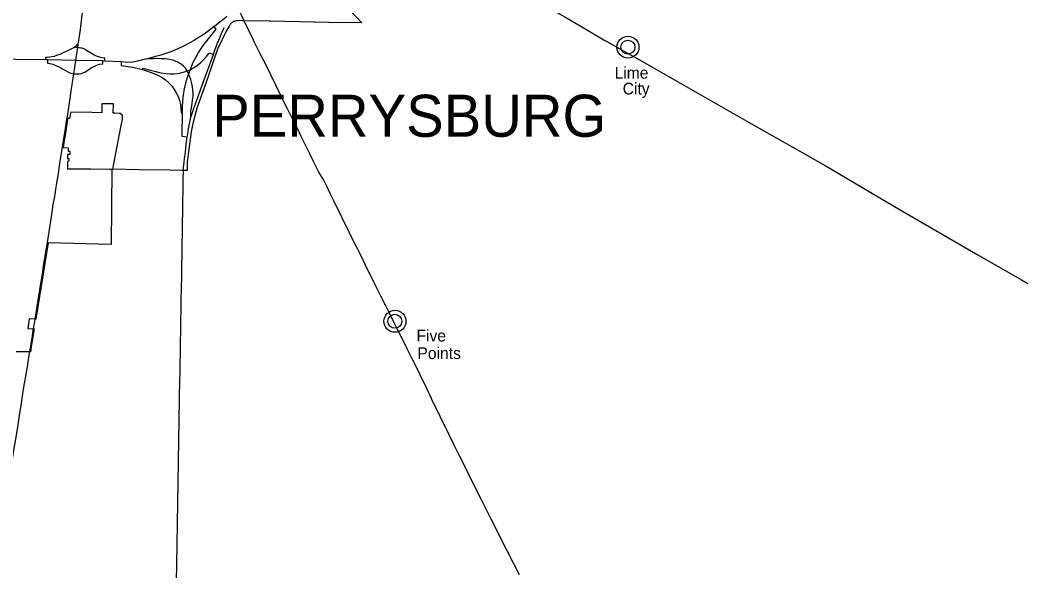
# Model space of a CAD drawing. Extents: x 0 to 851, y 0 to 440.
# Drawn here: x 318.5 to 378.4, y 277.3 to 310.2 of the extents above; entities that cross this region are included whole.
import ezdxf

# ---------------------------------------------------------------- set-up
doc = ezdxf.new("R2010")
doc.units = 0
for name, color, linetype in [('DV_X_Corp_Line', 7, 'Continuous'), ('GM_X_Corporation_Text', 7, 'Continuous'), ('GM_X_Interchange_Ramps', 7, 'Continuous'), ('GM_X_Interstate_Route', 7, 'Continuous'), ('GM_X_State_Route', 7, 'Continuous'), ('GM_X_US_Route', 7, 'Continuous')]:
    doc.layers.add(name, color=color, linetype=linetype)

msp = doc.modelspace()

# ---------------------------------------------------------------- linework, layer by layer
at = {"layer": 'DV_X_Corp_Line'}
msp.add_lwpolyline([(337.242, 311.829), (338.909, 310.055), (336.942, 310.078), (336.895, 310.078), (336.101, 310.09), (336.045, 310.09), (333.446, 310.144), (333.379, 310.145), (331.872, 310.178), (331.761, 310.178), (331.535, 310.182), (331.471, 310.18), (331.435, 310.177), (331.399, 310.172), (331.328, 310.155), (331.279, 310.138), (331.246, 310.123), (331.217, 310.107), (331.17, 310.077), (331.134, 310.051), (331.115, 310.035), (331.084, 310.004), (331.057, 309.973), (331.029, 309.936), (331.015, 309.916), (331.001, 309.894), (330.981, 309.857), (330.821, 309.598), (330.284, 308.48), (329.559, 306.323), (329.061, 304.951), (328.806, 304.038), (328.717, 303.553), (328.475, 301.76), (328.477, 301.238), (328.347, 301.238), (328.135, 301.241), (327.429, 301.254), (325.615, 301.283), (324.045, 301.309), (324.098, 301.63), (324.352, 302.983), (324.543, 303.915), (324.607, 304.272), (324.62, 304.515), (324.479, 304.63), (324.425, 304.64), (324.148, 304.651), (324.064, 304.653), (324.069, 305.218), (323.374, 305.218), (323.375, 304.672), (322.777, 304.695), (321.54, 304.726), (321.498, 304.567), (321.453, 304.338), (321.343, 304.338), (321.331, 304.289), (321.266, 303.88), (321.204, 303.471), (321.136, 303.034), (321.068, 302.601), (321.381, 302.591), (321.379, 302.396), (321.475, 302.395), (321.47, 302.184), (321.335, 302.187), (321.329, 301.964), (321.402, 301.964), (321.402, 301.794), (321.334, 301.783), (321.327, 301.737), (321.327, 301.341), (322.718, 301.329), (323.846, 301.311), (323.982, 301.309), (323.935, 296.813), (320.175, 296.928), (319.439, 292.37), (319.041, 292.378), (318.956, 291.817), (319.273, 291.787), (319.342, 291.787), (319.168, 290.718), (319.118, 290.411), (319.048, 290.414), (318.275, 290.42)], dxfattribs=at)
for centre, radius in [((354.787, 308.599), 0.658), ((354.787, 308.599), 0.417), ((340.876, 292.238), 0.658), ((340.876, 292.238), 0.417)]:
    msp.add_circle(centre, radius, dxfattribs=at)
at = {"layer": 'GM_X_Interchange_Ramps'}
for points in [[(321.975, 308.755), (321.913, 308.764), (321.857, 308.688), (321.801, 308.632), (321.724, 308.574), (321.604, 308.513), (320.866, 308.168), (320.678, 308.092), (320.541, 308.049), (320.397, 308.016), (320.265, 307.996), (320.09, 307.978), (320.022, 307.976), (320.02, 307.851)], [(321.949, 308.578), (321.884, 308.588), (321.789, 308.577), (321.733, 308.562), (321.724, 308.574)], [(323.557, 307.771), (323.559, 307.935), (323.414, 307.963), (323.242, 308.006), (323.069, 308.067), (322.861, 308.168), (322.656, 308.288), (322.428, 308.422), (322.301, 308.493), (322.199, 308.531), (322.123, 308.549), (322.037, 308.564), (321.949, 308.578)], [(320.133, 307.84), (320.13, 307.639), (320.283, 307.615), (320.465, 307.575), (320.64, 307.509), (320.856, 307.4), (321.383, 307.098), (321.464, 307.062), (321.538, 307.045), (321.639, 307.029), (321.708, 307.017)], [(321.708, 307.017), (321.793, 307.006), (321.923, 307.004), (322.03, 307.004), (322.154, 307.024), (322.253, 307.06), (322.359, 307.113), (322.75, 307.359), (322.904, 307.448), (323.013, 307.504), (323.127, 307.547), (323.252, 307.58), (323.376, 307.598), (323.436, 307.6), (323.44, 307.778)]]:
    msp.add_lwpolyline(points, dxfattribs=at)
at = {"layer": 'GM_X_Interstate_Route'}
for points in [[(321.825, 307.801), (320.133, 307.84), (320.02, 307.851), (312.929, 307.924), (311.76, 307.955), (311.222, 307.978), (310.795, 308.013), (310.42, 308.043), (310.05, 308.113), (309.736, 308.178), (309.383, 308.257), (309.023, 308.354), (308.624, 308.464), (308.248, 308.584), (307.869, 308.711), (307.566, 308.836), (307.238, 308.986), (306.945, 309.115), (306.66, 309.253), (306.342, 309.43), (306.144, 309.54)], [(328.702, 304.417), (328.778, 304.63), (328.876, 304.96), (328.985, 305.279), (329.125, 305.655), (329.272, 306.061), (329.427, 306.483), (329.564, 306.859), (329.711, 307.251), (329.88, 307.714), (330.039, 308.163), (330.135, 308.429), (330.272, 308.801), (330.358, 309.007), (330.458, 309.26), (330.553, 309.469), (330.624, 309.618), (330.687, 309.767)], [(326.083, 307.901), (325.804, 307.841), (325.516, 307.769), (325.234, 307.706), (324.875, 307.69), (324.533, 307.721), (323.557, 307.771), (323.44, 307.778), (321.825, 307.801)], [(328.263, 301.424), (328.27, 301.531), (328.31, 301.926), (328.371, 302.331), (328.423, 302.796), (328.485, 303.245), (328.509, 303.408), (328.564, 303.722), (328.644, 304.113), (328.702, 304.417)], [(328.047, 288.819), (328.057, 289.059), (328.067, 289.71), (328.077, 290.355), (328.083, 290.999), (328.101, 291.667), (328.1, 292.298), (328.109, 292.895), (328.121, 293.489), (328.13, 294.214), (328.151, 294.888), (328.158, 295.559), (328.168, 296.19), (328.178, 296.817), (328.192, 297.492), (328.194, 298.109), (328.208, 298.763), (328.221, 299.387), (328.235, 300.055), (328.241, 300.693), (328.252, 301.24)], [(328.252, 301.24), (328.252, 301.24), (328.259, 301.359), (328.263, 301.424)], [(327.831, 276.758), (327.849, 277.678), (328.047, 288.819)]]:
    msp.add_lwpolyline(points, dxfattribs=at)
at = {"layer": 'GM_X_State_Route'}
for points in [[(331.883, 310.167), (331.863, 310.207), (331.716, 310.5), (331.557, 310.836), (331.423, 311.11)], [(322.073, 309.392), (322.114, 309.662), (322.188, 310.35), (322.215, 310.525), (322.269, 310.761)], [(330.853, 310.435), (330.685, 310.298), (330.426, 310.09), (330.214, 309.917), (330.077, 309.814), (329.727, 309.544), (329.489, 309.379), (329.227, 309.207), (328.918, 309.017), (328.599, 308.834), (328.291, 308.671), (327.919, 308.499), (327.51, 308.321), (327.21, 308.211), (326.909, 308.126), (326.66, 308.063), (326.445, 308.009), (326.083, 307.901)], [(332.384, 309.131), (332.176, 309.559), (331.883, 310.167)], [(321.825, 307.801), (321.949, 308.578), (321.975, 308.755), (322.073, 309.392)], [(330.077, 309.814), (330.183, 309.675), (329.813, 309.197), (329.495, 308.803), (329.338, 308.587), (329.16, 308.299), (328.989, 307.993), (328.821, 307.676), (328.706, 307.416), (328.648, 307.252), (328.561, 307.008), (328.5, 306.839), (328.374, 306.447), (328.3, 306.111), (328.233, 305.759), (328.196, 305.374), (328.182, 305.001), (328.176, 304.687), (328.151, 303.31), (328.151, 303.294), (328.485, 303.245)], [(334.106, 305.637), (334.055, 305.745), (333.182, 307.526), (332.842, 308.202), (332.483, 308.926), (332.39, 309.118), (332.384, 309.131)], [(325.808, 307.261), (325.833, 307.348), (326.207, 307.247), (326.602, 307.145), (326.904, 307.075), (327.193, 307.026), (327.447, 307.011), (327.681, 307.002), (327.916, 307.03), (328.106, 307.07), (328.312, 307.126), (328.475, 307.179), (328.514, 307.192), (328.648, 307.252), (328.717, 307.283), (328.9, 307.387), (329.096, 307.526), (329.282, 307.682), (329.459, 307.843), (329.627, 308.041), (329.768, 308.23), (329.785, 308.255), (330.039, 308.163)], [(321.54, 305.86), (321.708, 307.017), (321.825, 307.801)], [(324.533, 307.721), (324.537, 307.506), (325.227, 307.401), (325.729, 307.284), (325.808, 307.261), (326.098, 307.176), (326.487, 307.037), (326.76, 306.911), (326.975, 306.796), (327.183, 306.644), (327.385, 306.475), (327.551, 306.293), (327.696, 306.078), (327.815, 305.882), (327.931, 305.646), (328.013, 305.412), (328.074, 305.181), (328.105, 304.956), (328.122, 304.688), (328.176, 304.687)], [(328.702, 304.417), (328.704, 304.773), (328.73, 304.984), (328.777, 305.238), (328.802, 305.435), (328.828, 305.679), (328.832, 305.834), (328.821, 306.045), (328.796, 306.227), (328.751, 306.44), (328.694, 306.673), (328.603, 306.917), (328.561, 307.008), (328.527, 307.08), (328.475, 307.179), (328.454, 307.22), (328.37, 307.343), (328.253, 307.463), (328.119, 307.577), (328, 307.651), (327.915, 307.703), (327.674, 307.8), (327.435, 307.86), (327.159, 307.897), (326.917, 307.907), (326.641, 307.919), (326.424, 307.912), (326.083, 307.901)], [(321.371, 304.73), (321.512, 305.667), (321.54, 305.86)], [(348.313, 277.112), (347.941, 277.85), (347.582, 278.544), (347.309, 279.078), (347.034, 279.619), (346.624, 280.431), (346.303, 281.064), (346.043, 281.577), (345.832, 281.999), (345.582, 282.492), (345.333, 283), (345.083, 283.502), (344.75, 284.172), (344.417, 284.851), (344.094, 285.508), (343.083, 287.579), (343.06, 287.625), (342.761, 288.269), (342.38, 289.041), (342.158, 289.506), (341.91, 289.999), (341.634, 290.553), (341.31, 291.203), (341.04, 291.75), (340.831, 292.154), (340.589, 292.641), (340.332, 293.161), (340.043, 293.746), (339.767, 294.293), (339.474, 294.868), (339.227, 295.365), (338.98, 295.881), (338.754, 296.337), (338.656, 296.536), (338.561, 296.731), (338.275, 297.299), (338.018, 297.816), (337.812, 298.24), (337.625, 298.631), (337.437, 299.005), (337.228, 299.427), (337.012, 299.872), (336.806, 300.297), (336.625, 300.654), (336.344, 301.134), (336.033, 301.741), (335.801, 302.223), (335.474, 302.878), (335.284, 303.267), (335.072, 303.699), (334.783, 304.277), (334.482, 304.878), (334.332, 305.184), (334.106, 305.637)], [(321.304, 304.371), (321.323, 304.479), (321.363, 304.686), (321.371, 304.73)], [(321.026, 302.601), (321.093, 303.036), (321.163, 303.479), (321.224, 303.882), (321.291, 304.299), (321.298, 304.338), (321.304, 304.371)], [(320.836, 301.371), (320.836, 301.371), (320.861, 301.513), (320.902, 301.785), (320.936, 302.022), (320.963, 302.196), (320.976, 302.277)], [(320.976, 302.277), (321.026, 302.601)], [(320.702, 300.496), (320.739, 300.71), (320.792, 301.071), (320.81, 301.196)], [(320.81, 301.196), (320.836, 301.371)], [(320.589, 299.797), (320.637, 300.113), (320.702, 300.496)], [(320.117, 296.825), (320.134, 296.935), (320.372, 298.466), (320.485, 299.2), (320.574, 299.695), (320.589, 299.797)], [(319.64, 293.853), (319.705, 294.264), (319.833, 295.056), (319.9, 295.535), (320.046, 296.378), (320.117, 296.825)], [(319.393, 292.369), (319.5, 292.974), (319.588, 293.523), (319.64, 293.853)], [(319.31, 291.84), (319.319, 291.894), (319.393, 292.369)], [(319.081, 290.432), (319.097, 290.525), (319.215, 291.233), (319.31, 291.84)], [(317.965, 283.565), (318.056, 284.051), (318.21, 284.99), (318.342, 285.798), (318.465, 286.621), (318.58, 287.355), (318.674, 287.903), (318.734, 288.303), (318.84, 288.954), (318.934, 289.522), (319.023, 290.102), (319.081, 290.432)]]:
    msp.add_lwpolyline(points, dxfattribs=at)
at = {"layer": 'GM_X_US_Route'}
for points in [[(347.744, 312.263), (351.03, 310.415), (352.721, 309.407)], [(352.721, 309.407), (352.779, 309.372), (353.25, 309.088)], [(353.25, 309.088), (353.406, 309.004)], [(353.406, 309.004), (353.52, 308.944), (354.303, 308.506), (355.805, 307.659), (357.716, 306.564), (362.171, 304.029), (366.565, 301.541), (371.042, 298.882), (375.674, 296.195), (378.29, 294.708)], [(378.29, 294.708), (378.668, 294.493)]]:
    msp.add_lwpolyline(points, dxfattribs=at)

# ---------------------------------------------------------------- texts
at = {"layer": 'DV_X_Corp_Line'}
for s, p in [('Lime', (353.99, 306.722)), ('City', (354.474, 305.776)), ('Five', (342.165, 291.032)), ('Points', (342.221, 289.985))]:
    msp.add_text(s, height=0.6979, rotation=0.00001, dxfattribs=at).set_placement(p)
at = {"layer": 'GM_X_Corporation_Text'}
msp.add_text('PERRYSBURG', height=2.5126, rotation=0.00001, dxfattribs=at).set_placement((329.971, 303.248))

doc.saveas('drawing.dxf')
